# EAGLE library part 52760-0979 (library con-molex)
MOLEX Connector SD-52760-**79 Source: 52760-1079_sd molex.pdf
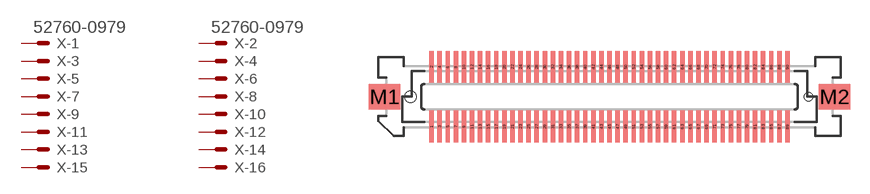
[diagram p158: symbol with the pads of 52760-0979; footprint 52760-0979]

Designator prefix X; gates -1=MV -2=MV -3=M -4=M -5=M -6=M -7=M -8=M -9=M -10=M -11=M -12=M -13=M -14=M -15=M -16=M -17=M -18=M -19=M -20=M -21=M -22=M -23=M -24=M -25=M -26=M -27=M -28=M -29=M -30=M -31=M -32=M -33=M -34=M -35=M -36=M -37=M -38=M -39=M -40=M -41=M -42=M -43=M -44=M -45=M -46=M -47=M -48=M -49=M -50=M -51=M -52=M -53=M -54=M -55=M -56=M -57=M -58=M -59=M -60=M -61=M -62=M -63=M -64=M -65=M -66=M -67=M -68=M -69=M -70=M -71=M -72=M -73=M -74=M -75=M -76=M -77=M -78=M -79=M -80=M -81=M -82=M -83=M -84=M -85=M -86=M -87=M -88=M -89=M -90=M

## 52760-0979 (MPN: 52760-0979; OC_FARNELL: unknown; OC_NEWARK: 92M6432)  [52760-0979]
1  -1:S  pas
2  -2:S  pas
3  -3:S  pas
4  -4:S  pas
5  -5:S  pas
6  -6:S  pas
7  -7:S  pas
8  -8:S  pas
9  -9:S  pas
10  -10:S  pas
11  -11:S  pas
12  -12:S  pas
13  -13:S  pas
14  -14:S  pas
15  -15:S  pas
16  -16:S  pas
17  -17:S  pas
18  -18:S  pas
19  -19:S  pas
20  -20:S  pas
21  -21:S  pas
22  -22:S  pas
23  -23:S  pas
24  -24:S  pas
25  -25:S  pas
26  -26:S  pas
27  -27:S  pas
28  -28:S  pas
29  -29:S  pas
30  -30:S  pas
31  -31:S  pas
32  -32:S  pas
33  -33:S  pas
34  -34:S  pas
35  -35:S  pas
36  -36:S  pas
37  -37:S  pas
38  -38:S  pas
39  -39:S  pas
40  -40:S  pas
41  -41:S  pas
42  -42:S  pas
43  -43:S  pas
44  -44:S  pas
45  -45:S  pas
46  -46:S  pas
47  -47:S  pas
48  -48:S  pas
49  -49:S  pas
50  -50:S  pas
51  -51:S  pas
52  -52:S  pas
53  -53:S  pas
54  -54:S  pas
55  -55:S  pas
56  -56:S  pas
57  -57:S  pas
58  -58:S  pas
59  -59:S  pas
60  -60:S  pas
61  -61:S  pas
62  -62:S  pas
63  -63:S  pas
64  -64:S  pas
65  -65:S  pas
66  -66:S  pas
67  -67:S  pas
68  -68:S  pas
69  -69:S  pas
70  -70:S  pas
71  -71:S  pas
72  -72:S  pas
73  -73:S  pas
74  -74:S  pas
75  -75:S  pas
76  -76:S  pas
77  -77:S  pas
78  -78:S  pas
79  -79:S  pas
80  -80:S  pas
81  -81:S  pas
82  -82:S  pas
83  -83:S  pas
84  -84:S  pas
85  -85:S  pas
86  -86:S  pas
87  -87:S  pas
88  -88:S  pas
89  -89:S  pas
90  -90:S  pas

## Footprint 52760-0979 (pad centres in mm)
MOLEX Connector SD-52760-**79 Source: 52760-1079_sd molex.pdf
smd 0.35 x 2.5: 1 -13.97,-2.35; 2 -13.97,2.35; 3 -13.335,-2.35; 4 -13.335,2.35; 5 -12.7,-2.35; 6 -12.7,2.35; 7 -12.065,-2.35; 8 -12.065,2.35; 9 -11.43,-2.35; 10 -11.43,2.35; 11 -10.795,-2.35; 12 -10.795,2.35; 13 -10.16,-2.35; 14 -10.16,2.35; 15 -9.525,-2.35; 16 -9.525,2.35; 17 -8.89,-2.35; 18 -8.89,2.35; 19 -8.255,-2.35; 20 -8.255,2.35; 21 -7.62,-2.35; 22 -7.62,2.35; 23 -6.985,-2.35; 24 -6.985,2.35; 25 -6.35,-2.35; 26 -6.35,2.35; 27 -5.715,-2.35; 28 -5.715,2.35; 29 -5.08,-2.35; 30 -5.08,2.35; 31 -4.445,-2.35; 32 -4.445,2.35; 33 -3.81,-2.35; 34 -3.81,2.35; 35 -3.175,-2.35; 36 -3.175,2.35; 37 -2.54,-2.35; 38 -2.54,2.35; 39 -1.905,-2.35; 40 -1.905,2.35; 41 -1.27,-2.35; 42 -1.27,2.35; 43 -0.635,-2.35; 44 -0.635,2.35; 45 0,-2.35; 46 0,2.35; 47 0.635,-2.35; 48 0.635,2.35; 49 1.27,-2.35; 50 1.27,2.35; 51 1.905,-2.35; 52 1.905,2.35; 53 2.54,-2.35; 54 2.54,2.35; 55 3.175,-2.35; 56 3.175,2.35; 57 3.81,-2.35; 58 3.81,2.35; 59 4.445,-2.35; 60 4.445,2.35; 61 5.08,-2.35; 62 5.08,2.35; 63 5.715,-2.35; 64 5.715,2.35; 65 6.35,-2.35; 66 6.35,2.35; 67 6.985,-2.35; 68 6.985,2.35; 69 7.62,-2.35; 70 7.62,2.35; 71 8.255,-2.35; 72 8.255,2.35; 73 8.89,-2.35; 74 8.89,2.35; 75 9.525,-2.35; 76 9.525,2.35; 77 10.16,-2.35; 78 10.16,2.35; 79 10.795,-2.35; 80 10.795,2.35; 81 11.43,-2.35; 82 11.43,2.35; 83 12.065,-2.35; 84 12.065,2.35; 85 12.7,-2.35; 86 12.7,2.35; 87 13.335,-2.35; 88 13.335,2.35; 89 13.97,-2.35; 90 13.97,2.35
smd 2.5 x 2: M1 -17.663,0; M2 17.663,0
hole 0.9 at -15.623,0
hole 0.7 at 15.623,0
